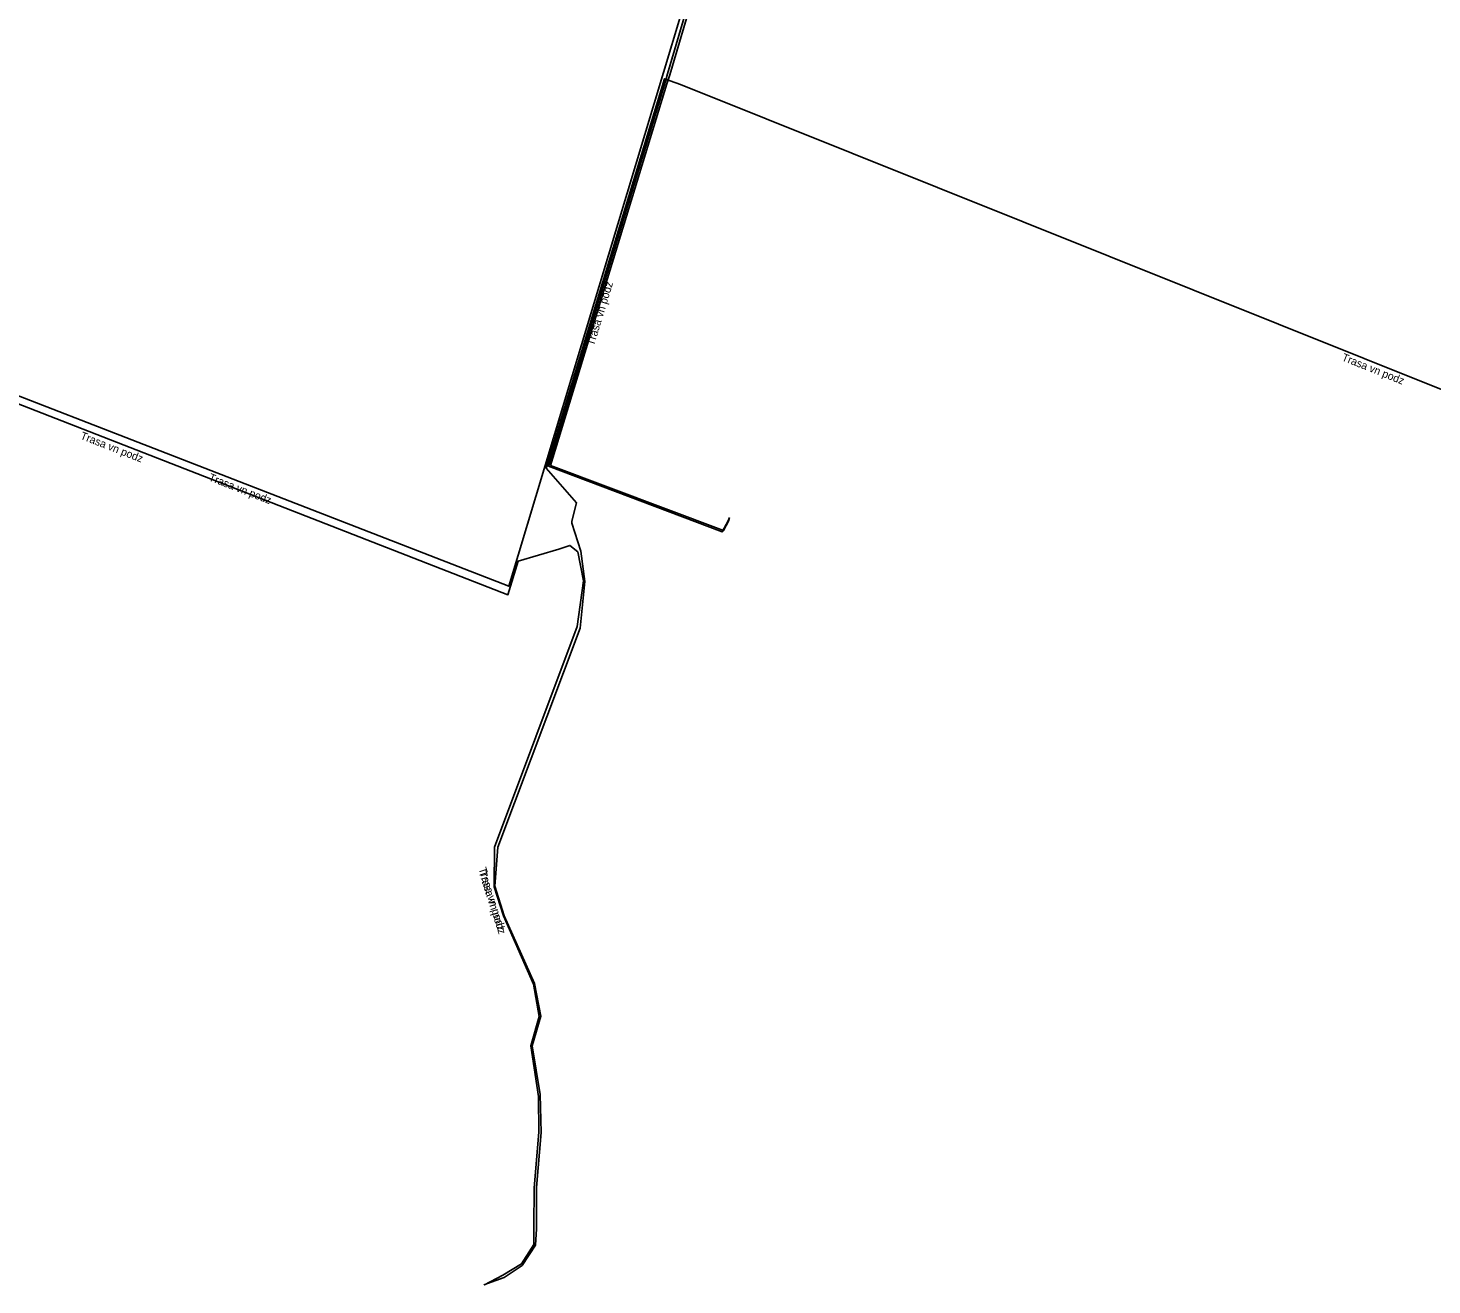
# Model space of a CAD drawing. Extents: x -875087 to -874407, y -1056142 to -1055396.
# Drawn here: x -874634 to -874544, y -1055795.4 to -1055714.8 of the extents above; entities that cross this region are included whole.
import ezdxf

# ---------------------------------------------------------------- set-up
doc = ezdxf.new("R2010")
doc.units = 0
for name, color, linetype in [('Popiskový text - Ostatní atributy Trasy', 7, 'Continuous'), ('Spojnice NN', 7, 'Continuous'), ('Spojnice VN', 7, 'Continuous')]:
    doc.layers.add(name, color=color, linetype=linetype)

msp = doc.modelspace()

# ---------------------------------------------------------------- linework, layer by layer
at = {"layer": 'Spojnice NN'}
for points in [[(-874671.626, -1055675.739), (-874672.141, -1055676.099), (-874672.092, -1055676.233), (-874668.053, -1055686.512), (-874655.676, -1055691.441), (-874653.632, -1055685.729), (-874636.773, -1055691.664), (-874636.395, -1055690.518), (-874634.684, -1055683.784), (-874614.188, -1055689.954), (-874599.121, -1055694.492), (-874587.051, -1055697.614), (-874589.414, -1055705.679), (-874592.971, -1055717.789), (-874593.107, -1055718.278), (-874600.606, -1055742.939), (-874589.46, -1055747.145), (-874589.079, -1055746.438), (-874588.99, -1055746.232)], [(-874550.945, -1055689.783), (-874550.944, -1055689.777), (-874551.044, -1055689.294), (-874550.044, -1055682.572), (-874573.744, -1055678.145), (-874577.328, -1055677.819), (-874579.364, -1055678.227), (-874580.83, -1055678.552), (-874581.37, -1055679.123), (-874586.832, -1055697.422), (-874589.237, -1055705.685), (-874592.825, -1055717.837), (-874593.016, -1055718.411), (-874600.462, -1055742.884), (-874589.38, -1055747.068), (-874589.064, -1055746.456), (-874588.99, -1055746.232)]]:
    msp.add_lwpolyline(points, dxfattribs=at)
at = {"layer": 'Spojnice VN'}
for points in [[(-874577.524, -1055665.497), (-874603.145, -1055750.63), (-874659.412, -1055728.792), (-874653.483, -1055710.725), (-874660.188, -1055679.228), (-874664.248, -1055677.369), (-874671.501, -1055675.744)], [(-874599.107, -1055746.454), (-874598.81, -1055745.29), (-874600.741, -1055743.065), (-874593.159, -1055718.093), (-874592.144, -1055718.468)], [(-874592.144, -1055718.468), (-874531.837, -1055742.641), (-874529.864, -1055743.504), (-874527.952, -1055744.491), (-874527.212, -1055745.231), (-874527.15, -1055745.848), (-874527.212, -1055746.094), (-874528.137, -1055749.239), (-874527.89, -1055750.781), (-874527.027, -1055752.322), (-874527.336, -1055753.124), (-874528.753, -1055753.741), (-874529.679, -1055754.604), (-874536.092, -1055767.492), (-874536.524, -1055768.417), (-874536.524, -1055769.589)], [(-874656.398, -1055730.431), (-874603.204, -1055751.177), (-874602.553, -1055749.028), (-874599.932, -1055748.248)], [(-874604.737, -1055795.429), (-874603.45, -1055794.95), (-874602.28, -1055794.18), (-874601.43, -1055792.87), (-874601.38, -1055791.84), (-874601.37, -1055789.18), (-874601.08, -1055785.65), (-874601.13, -1055783.22), (-874601.64, -1055780.1), (-874601.1, -1055778.19), (-874601.5, -1055776.11), (-874603.45, -1055771.77), (-874604.05, -1055769.86), (-874603.85, -1055767.37), (-874598.58, -1055753.32), (-874598.28, -1055750.32), (-874598.53, -1055748.39), (-874599.11, -1055746.58), (-874599.107, -1055746.454)], [(-874599.932, -1055748.248), (-874599.23, -1055748.01), (-874598.71, -1055748.43), (-874598.36, -1055750.28), (-874598.77, -1055753.21), (-874604.06, -1055767.36), (-874604.09, -1055769.91), (-874603.49, -1055771.77), (-874601.56, -1055776.14), (-874601.2, -1055778.21), (-874601.74, -1055780.09), (-874601.24, -1055783.34), (-874601.23, -1055785.64), (-874601.53, -1055789.2), (-874601.54, -1055791.72), (-874601.54, -1055792.83), (-874602.33, -1055794.08), (-874603.52, -1055794.8), (-874604.697, -1055795.429)]]:
    msp.add_lwpolyline(points, dxfattribs=at)

# ---------------------------------------------------------------- texts
at = {"layer": 'Popiskový text - Ostatní atributy Trasy'}
for rotation, p in [(73.11086, (-874597.688, -1055735.247)), (338.15773, (-874549.797, -1055736.142)), (338.69417, (-874630.649, -1055741.171)), (338.78922, (-874622.428, -1055743.843)), (287.43939, (-874605.084, -1055768.737)), (287.8787, (-874605.08, -1055768.958))]:
    msp.add_text('Trasa vn podz', height=0.5, rotation=rotation, dxfattribs=at).set_placement(p)

doc.saveas('drawing.dxf')
